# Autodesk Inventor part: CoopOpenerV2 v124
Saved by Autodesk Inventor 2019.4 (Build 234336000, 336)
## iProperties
Created: 2020-02
Part Number: CoopOpenerV2 v124
Material: Generic
Document SubType Name: Modeling
Designer: Administrator
Density: 1 g/cm^3
Appearance: Default
Author: Administrator
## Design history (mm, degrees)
feature "Body1"
feature "Body2"
feature "Body1 (1)"
feature "Body2 (1)"
feature "Body4"
feature "Body6"
body "Solid1"
body "Solid2"
body "Solid3"
body "Solid4"
body "Solid5"
body "Solid6"
